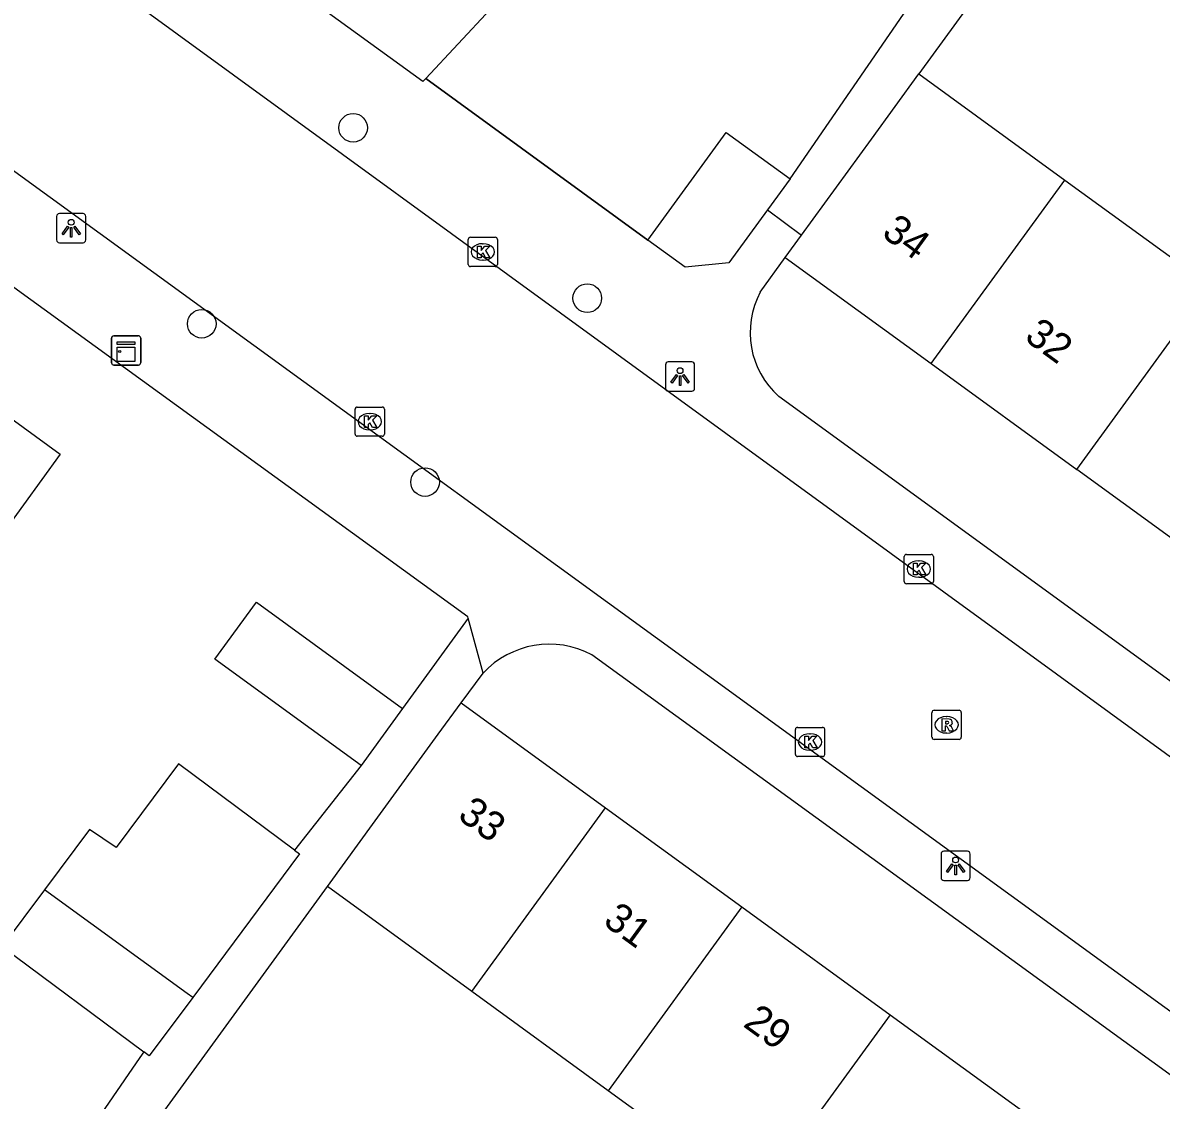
# Model space of a CAD drawing. Extents: x 159675 to 160530, y 382179 to 382901.
# Drawn here: x 160139.21 to 160178.13, y 382590.02 to 382626.86 of the extents above; entities that cross this region are included whole.
import ezdxf

# ---------------------------------------------------------------- set-up
doc = ezdxf.new("R2010")
doc.units = 0
for name, color, linetype in [('IMGEO_Boom', 7, 'Continuous'), ('IMGEO_Kast', 7, 'Continuous'), ('IMGEO_Kolk', 7, 'Continuous'), ('IMGEO_Lichtpunt', 7, 'Continuous'), ('IMGEO_Muur', 7, 'Continuous'), ('IMGEO_Pand', 7, 'Continuous'), ('IMGEO_Pand_nummerreeks', 7, 'Continuous'), ('IMGEO_Rijbaan_lokaal_open', 7, 'Continuous'), ('IMGEO_Rioolput', 7, 'Continuous'), ('IMGEO_Voetpad_open', 7, 'Continuous')]:
    doc.layers.add(name, color=color, linetype=linetype)

msp = doc.modelspace()

# ---------------------------------------------------------------- linework, layer by layer
at = {"layer": 'IMGEO_Boom'}
for centre in [(160150.503, 382623.268), (160158.508, 382617.444), (160145.327, 382616.568), (160152.962, 382611.156)]:
    msp.add_circle(centre, 0.489, dxfattribs=at)
at = {"layer": 'IMGEO_Kast'}
for p, q in [((160142.243, 382615.231), (160142.243, 382616.072)), ((160142.243, 382616.072), (160142.243, 382615.231)), ((160142.318, 382616.156), (160143.159, 382616.156)), ((160143.159, 382616.156), (160142.318, 382616.156)), ((160143.243, 382616.081), (160143.243, 382615.24)), ((160143.243, 382615.24), (160143.243, 382616.081)), ((160143.168, 382615.156), (160142.327, 382615.156)), ((160142.327, 382615.156), (160143.168, 382615.156))]:
    msp.add_line(p, q, dxfattribs=at)
for points in [[(160142.438, 382615.946), (160143.038, 382615.946), (160143.038, 382615.861), (160142.438, 382615.861), (160142.438, 382615.946)], [(160142.438, 382615.771), (160143.038, 382615.771), (160143.038, 382615.282), (160142.438, 382615.282), (160142.438, 382615.771)]]:
    msp.add_lwpolyline(points, dxfattribs=at)
msp.add_circle((160142.522, 382615.62), 0.0377, dxfattribs=at)
for centre, start, end in [((160142.321, 382616.078), 92.4484, 184.2845), ((160142.321, 382616.078), 92.4484, 184.2845), ((160143.165, 382616.078), 2.4484, 94.2845), ((160143.165, 382616.078), 2.4484, 94.2845), ((160142.321, 382615.234), 182.4484, 274.2845), ((160142.321, 382615.234), 182.4484, 274.2845), ((160143.165, 382615.234), 272.4484, 4.2845), ((160143.165, 382615.234), 272.4484, 4.2845)]:
    msp.add_arc(centre, 0.0779, start, end, dxfattribs=at)
at = {"layer": 'IMGEO_Kolk'}
for p, q in [((160154.51, 382619.526), (160155.362, 382619.526)), ((160154.435, 382618.6), (160154.435, 382619.452)), ((160154.923, 382619.306), (160154.948, 382619.306)), ((160155.436, 382619.452), (160155.436, 382618.6)), ((160154.946, 382618.746), (160154.921, 382618.746)), ((160155.362, 382618.526), (160154.51, 382618.526)), ((160150.646, 382613.723), (160151.498, 382613.723)), ((160150.571, 382612.797), (160150.571, 382613.649)), ((160151.059, 382613.503), (160151.084, 382613.503)), ((160151.572, 382613.649), (160151.572, 382612.797)), ((160151.082, 382612.943), (160151.057, 382612.943)), ((160151.498, 382612.723), (160150.646, 382612.723)), ((160169.415, 382608.682), (160170.267, 382608.682)), ((160169.34, 382607.756), (160169.34, 382608.608)), ((160169.828, 382608.462), (160169.853, 382608.462)), ((160170.341, 382608.608), (160170.341, 382607.756)), ((160169.851, 382607.902), (160169.826, 382607.902)), ((160170.267, 382607.682), (160169.415, 382607.682)), ((160165.621, 382601.846), (160165.621, 382602.698)), ((160165.696, 382602.772), (160166.548, 382602.772)), ((160166.109, 382602.552), (160166.134, 382602.552)), ((160166.622, 382602.698), (160166.622, 382601.846)), ((160166.548, 382601.772), (160165.696, 382601.772)), ((160166.132, 382601.992), (160166.107, 382601.992))]:
    msp.add_line(p, q, dxfattribs=at)
for points in [[(160154.51, 382619.526), (160155.362, 382619.526)], [(160154.435, 382618.6), (160154.435, 382619.452)], [(160154.756, 382619.226), (160154.879, 382619.226), (160154.879, 382619.075), (160155.009, 382619.226), (160155.173, 382619.226), (160155.027, 382619.075), (160155.18, 382618.826), (160155.028, 382618.826), (160154.943, 382618.99), (160154.879, 382618.923), (160154.879, 382618.826), (160154.756, 382618.826), (160154.756, 382619.226)], [(160155.436, 382619.452), (160155.436, 382618.6)], [(160155.362, 382618.526), (160154.51, 382618.526)], [(160150.646, 382613.723), (160151.498, 382613.723)], [(160150.571, 382612.797), (160150.571, 382613.649)], [(160150.892, 382613.423), (160151.015, 382613.423), (160151.015, 382613.272), (160151.145, 382613.423), (160151.309, 382613.423), (160151.163, 382613.272), (160151.316, 382613.023), (160151.164, 382613.023), (160151.079, 382613.187), (160151.015, 382613.12), (160151.015, 382613.023), (160150.892, 382613.023), (160150.892, 382613.423)], [(160151.572, 382613.649), (160151.572, 382612.797)], [(160151.498, 382612.723), (160150.646, 382612.723)], [(160169.415, 382608.682), (160170.267, 382608.682)], [(160169.34, 382607.756), (160169.34, 382608.608)], [(160169.661, 382608.382), (160169.784, 382608.382), (160169.784, 382608.231), (160169.914, 382608.382), (160170.078, 382608.382), (160169.932, 382608.231), (160170.085, 382607.982), (160169.933, 382607.982), (160169.848, 382608.146), (160169.784, 382608.079), (160169.784, 382607.982), (160169.661, 382607.982), (160169.661, 382608.382)], [(160170.341, 382608.608), (160170.341, 382607.756)], [(160170.267, 382607.682), (160169.415, 382607.682)], [(160165.621, 382601.846), (160165.621, 382602.698)], [(160165.696, 382602.772), (160166.548, 382602.772)], [(160165.942, 382602.472), (160166.065, 382602.472), (160166.065, 382602.321), (160166.195, 382602.472), (160166.359, 382602.472), (160166.213, 382602.321), (160166.366, 382602.072), (160166.214, 382602.072), (160166.129, 382602.236), (160166.065, 382602.169), (160166.065, 382602.072), (160165.942, 382602.072), (160165.942, 382602.472)], [(160166.622, 382602.698), (160166.622, 382601.846)], [(160166.548, 382601.772), (160165.696, 382601.772)]]:
    msp.add_lwpolyline(points, dxfattribs=at)
for centre, start, end in [((160154.512, 382619.45), 91.552, 178.448), ((160154.512, 382619.45), 91.552, 178.448), ((160155.36, 382619.45), 1.552, 88.448), ((160155.36, 382619.45), 1.552, 88.448), ((160154.512, 382618.602), 181.552, 268.448), ((160154.512, 382618.602), 181.552, 268.448), ((160155.36, 382618.602), 271.552, 358.448), ((160155.36, 382618.602), 271.552, 358.448), ((160150.648, 382613.647), 91.552, 178.448), ((160150.648, 382613.647), 91.552, 178.448), ((160151.496, 382613.647), 1.552, 88.448), ((160151.496, 382613.647), 1.552, 88.448), ((160150.648, 382612.799), 181.552, 268.448), ((160150.648, 382612.799), 181.552, 268.448), ((160151.496, 382612.799), 271.552, 358.448), ((160151.496, 382612.799), 271.552, 358.448), ((160169.417, 382608.606), 91.552, 178.448), ((160169.417, 382608.606), 91.552, 178.448), ((160170.265, 382608.606), 1.552, 88.448), ((160170.265, 382608.606), 1.552, 88.448), ((160169.417, 382607.758), 181.552, 268.448), ((160169.417, 382607.758), 181.552, 268.448), ((160170.265, 382607.758), 271.552, 358.448), ((160170.265, 382607.758), 271.552, 358.448), ((160165.698, 382602.696), 91.552, 178.448), ((160165.698, 382602.696), 91.552, 178.448), ((160166.546, 382602.696), 1.552, 88.448), ((160166.546, 382602.696), 1.552, 88.448), ((160165.698, 382601.848), 181.552, 268.448), ((160165.698, 382601.848), 181.552, 268.448), ((160166.546, 382601.848), 271.552, 358.448), ((160166.546, 382601.848), 271.552, 358.448)]:
    msp.add_arc(centre, 0.0765, start, end, dxfattribs=at)
for centre, major_axis, ratio, start_param, end_param in [((160154.922, 382619.026), (-0.387, 0.002), 0.722429, 4.712389, 7.853982), ((160154.947, 382619.026), (-0.39, 0.002), 0.717154, 1.570796, 4.712389), ((160151.058, 382613.223), (-0.387, 0.002), 0.722429, 4.712389, 7.853982), ((160151.083, 382613.223), (-0.39, 0.002), 0.717154, 1.570796, 4.712389), ((160169.827, 382608.182), (-0.387, 0.002), 0.722429, 4.712389, 7.853982), ((160169.852, 382608.182), (-0.39, 0.002), 0.717154, 1.570796, 4.712389), ((160166.108, 382602.272), (-0.387, 0.002), 0.722429, 4.712389, 7.853982), ((160166.133, 382602.272), (-0.39, 0.002), 0.717154, 1.570796, 4.712389)]:
    msp.add_ellipse(centre, major_axis=major_axis, ratio=ratio, start_param=start_param, end_param=end_param, dxfattribs=at)
at = {"layer": 'IMGEO_Lichtpunt'}
for p, q in [((160141.269, 382620.335), (160140.461, 382620.335)), ((160141.269, 382620.335), (160140.461, 382620.335)), ((160140.367, 382620.24), (160140.367, 382619.433)), ((160140.367, 382620.24), (160140.367, 382619.433)), ((160141.363, 382619.433), (160141.363, 382620.24)), ((160141.363, 382619.433), (160141.363, 382620.24)), ((160140.461, 382619.339), (160141.269, 382619.339)), ((160140.461, 382619.339), (160141.269, 382619.339)), ((160162.083, 382615.263), (160161.275, 382615.263)), ((160162.083, 382615.263), (160161.275, 382615.263)), ((160161.181, 382615.168), (160161.181, 382614.361)), ((160161.181, 382615.168), (160161.181, 382614.361)), ((160162.177, 382614.361), (160162.177, 382615.168)), ((160162.177, 382614.361), (160162.177, 382615.168)), ((160161.275, 382614.267), (160162.083, 382614.267)), ((160161.275, 382614.267), (160162.083, 382614.267)), ((160171.503, 382598.535), (160170.695, 382598.535)), ((160171.503, 382598.535), (160170.695, 382598.535)), ((160170.601, 382598.44), (160170.601, 382597.633)), ((160170.601, 382598.44), (160170.601, 382597.633)), ((160171.597, 382597.633), (160171.597, 382598.44)), ((160171.597, 382597.633), (160171.597, 382598.44)), ((160170.695, 382597.539), (160171.503, 382597.539)), ((160170.695, 382597.539), (160171.503, 382597.539))]:
    msp.add_line(p, q, dxfattribs=at)
for points in [[(160140.741, 382619.904), (160140.78, 382619.876), (160140.592, 382619.614), (160140.554, 382619.641), (160140.741, 382619.904)], [(160140.953, 382619.876), (160140.991, 382619.903), (160141.178, 382619.641), (160141.139, 382619.613), (160140.953, 382619.876)], [(160140.843, 382619.856), (160140.89, 382619.856), (160140.89, 382619.534), (160140.843, 382619.534), (160140.843, 382619.856)], [(160161.555, 382614.832), (160161.594, 382614.804), (160161.406, 382614.542), (160161.368, 382614.569), (160161.555, 382614.832)], [(160161.657, 382614.784), (160161.704, 382614.784), (160161.704, 382614.462), (160161.657, 382614.462), (160161.657, 382614.784)], [(160161.767, 382614.804), (160161.805, 382614.831), (160161.992, 382614.569), (160161.953, 382614.541), (160161.767, 382614.804)], [(160170.975, 382598.104), (160171.014, 382598.076), (160170.826, 382597.814), (160170.788, 382597.841), (160170.975, 382598.104)], [(160171.187, 382598.076), (160171.225, 382598.103), (160171.412, 382597.841), (160171.373, 382597.813), (160171.187, 382598.076)], [(160171.077, 382598.056), (160171.124, 382598.056), (160171.124, 382597.734), (160171.077, 382597.734), (160171.077, 382598.056)]]:
    msp.add_lwpolyline(points, dxfattribs=at)
for centre in [(160140.866, 382620.038), (160161.68, 382614.966), (160171.1, 382598.238)]:
    msp.add_circle(centre, 0.0994, dxfattribs=at)
for centre, start, end in [((160140.461, 382620.24), 90, 180), ((160140.461, 382620.24), 90, 180), ((160141.269, 382620.24), 0, 90), ((160141.269, 382620.24), 0, 90), ((160140.461, 382619.433), 180, 270), ((160140.461, 382619.433), 180, 270), ((160141.269, 382619.433), 270, 0), ((160141.269, 382619.433), 270, 360), ((160161.275, 382615.168), 90, 180), ((160161.275, 382615.168), 90, 180), ((160162.083, 382615.168), 0, 90), ((160162.083, 382615.168), 0, 90), ((160161.275, 382614.361), 180, 270), ((160161.275, 382614.361), 180, 270), ((160162.083, 382614.361), 270, 0), ((160162.083, 382614.361), 270, 360), ((160170.695, 382598.44), 90, 180), ((160170.695, 382598.44), 90, 180), ((160171.503, 382598.44), 0, 90), ((160171.503, 382598.44), 0, 90), ((160170.695, 382597.633), 180, 270), ((160170.695, 382597.633), 180, 270), ((160171.503, 382597.633), 270, 0), ((160171.503, 382597.633), 270, 360)]:
    msp.add_arc(centre, 0.0946, start, end, dxfattribs=at)
at = {"layer": 'IMGEO_Muur'}
msp.add_lwpolyline([(160160.579, 382619.432), (160152.983, 382624.952)], dxfattribs=at)
at = {"layer": 'IMGEO_Pand'}
for points in [[(160156.441, 382634.037), (160159.44, 382631.857), (160155.204, 382627.327), (160152.983, 382624.952)], [(160152.983, 382624.952), (160152.887, 382624.85), (160146.308, 382629.63)], [(160165.83, 382619.594), (160168.219, 382622.878), (160169.844, 382625.113)], [(160169.844, 382625.113), (160174.833, 382621.484)], [(160160.579, 382619.432), (160163.255, 382623.113), (160165.439, 382621.525)], [(160165.439, 382621.525), (160164.668, 382620.465)], [(160170.266, 382615.205), (160174.833, 382621.484)], [(160174.833, 382621.484), (160179.808, 382617.866)], [(160164.668, 382620.465), (160163.351, 382618.653), (160161.857, 382618.503), (160160.579, 382619.432)], [(160165.277, 382618.834), (160165.83, 382619.594)], [(160165.277, 382618.834), (160170.266, 382615.205)], [(160175.241, 382611.587), (160179.808, 382617.866)], [(160130.542, 382611.402), (160134.322, 382616.601), (160140.492, 382612.116), (160136.713, 382606.917)], [(160170.266, 382615.205), (160175.241, 382611.587)], [(160179.995, 382608.129), (160175.241, 382611.587)], [(160150.775, 382601.469), (160145.778, 382605.101), (160147.195, 382607.051), (160152.192, 382603.418)], [(160149.623, 382597.332), (160151.252, 382599.572), (160153.407, 382602.535), (160154.192, 382603.615)], [(160154.192, 382603.615), (160159.129, 382600.024)], [(160152.192, 382603.418), (160150.775, 382601.469)], [(160148.493, 382598.578), (160144.535, 382601.523), (160142.407, 382598.663), (160141.485, 382599.284), (160139.948, 382597.218)], [(160154.559, 382593.742), (160159.129, 382600.024)], [(160159.129, 382600.024), (160163.793, 382596.632)], [(160148.493, 382598.578), (160148.673, 382598.444), (160145.02, 382593.532)], [(160154.559, 382593.742), (160149.623, 382597.332)], [(160139.948, 382597.218), (160138.506, 382595.279), (160143.351, 382591.675)], [(160145.02, 382593.532), (160144.833, 382593.668), (160139.948, 382597.218)], [(160163.793, 382596.632), (160159.224, 382590.349)], [(160163.793, 382596.632), (160168.857, 382592.948)], [(160145.02, 382593.532), (160143.536, 382591.538), (160143.351, 382591.675)], [(160159.224, 382590.349), (160154.559, 382593.742)], [(160168.857, 382592.948), (160164.287, 382586.666)], [(160168.857, 382592.948), (160173.849, 382589.318)], [(160164.287, 382586.666), (160159.224, 382590.349)]]:
    msp.add_lwpolyline(points, dxfattribs=at)
at = {"layer": 'IMGEO_Rijbaan_lokaal_open'}
for points in [[(160245.716, 382552.786), (160140.763, 382629.192), (160140.555, 382629.351)], [(160136.439, 382623.587), (160136.712, 382623.379), (160240.412, 382548.029)]]:
    msp.add_lwpolyline(points, dxfattribs=at)
at = {"layer": 'IMGEO_Rioolput'}
for p, q in [((160170.291, 382602.432), (160170.291, 382603.284)), ((160170.366, 382603.358), (160171.218, 382603.358)), ((160171.292, 382603.284), (160171.292, 382602.432)), ((160170.779, 382603.138), (160170.804, 382603.138)), ((160170.802, 382602.578), (160170.777, 382602.578)), ((160171.218, 382602.358), (160170.366, 382602.358))]:
    msp.add_line(p, q, dxfattribs=at)
for points in [[(160170.291, 382602.432), (160170.291, 382603.284)], [(160170.366, 382603.358), (160171.218, 382603.358)], [(160171.292, 382603.284), (160171.292, 382602.432)], [(160170.88, 382603.056), (160170.628, 382603.058), (160170.628, 382602.658)], [(160170.628, 382602.658), (160170.752, 382602.658), (160170.752, 382602.82), (160170.763, 382602.82)], [(160170.806, 382602.977), (160170.752, 382602.977), (160170.752, 382602.896)], [(160170.752, 382602.896), (160170.804, 382602.896)], [(160170.81, 382602.791), (160170.881, 382602.658), (160171.021, 382602.658), (160170.956, 382602.784)], [(160171.218, 382602.358), (160170.366, 382602.358)]]:
    msp.add_lwpolyline(points, dxfattribs=at)
for centre, radius, start, end in [((160170.368, 382603.282), 0.0765, 91.552, 178.448), ((160170.368, 382603.282), 0.0765, 91.552, 178.448), ((160171.216, 382603.282), 0.0765, 1.552, 88.448), ((160171.216, 382603.282), 0.0765, 1.552, 88.448), ((160170.762, 382602.767), 0.0533, 26.0293, 88.6989), ((160170.788, 382603.085), 0.19, 274.7715, 282.9687), ((160170.812, 382602.881), 0.0964, 77.0061, 93.1865), ((160170.826, 382602.938), 0.0378, 276.6634, 79.6772), ((160170.879, 382602.946), 0.109, 350.3612, 89.416), ((160170.877, 382602.946), 0.112, 277.5842, 350.9817), ((160170.861, 382602.731), 0.108, 29.5134, 73.7905), ((160170.368, 382602.434), 0.0765, 181.552, 268.448), ((160170.368, 382602.434), 0.0765, 181.552, 268.448), ((160171.216, 382602.434), 0.0765, 271.552, 358.448), ((160171.216, 382602.434), 0.0765, 271.552, 358.448)]:
    msp.add_arc(centre, radius, start, end, dxfattribs=at)
for centre, major_axis, ratio, start_param, end_param in [((160170.778, 382602.858), (-0.387, 0.002), 0.722429, 4.712389, 7.853982), ((160170.803, 382602.858), (-0.39, 0.002), 0.717154, 1.570796, 4.712389)]:
    msp.add_ellipse(centre, major_axis=major_axis, ratio=ratio, start_param=start_param, end_param=end_param, dxfattribs=at)
at = {"layer": 'IMGEO_Voetpad_open'}
for points in [[(160180.693, 382633.904), (160177.781, 382636.024), (160169.844, 382625.113)], [(160165.439, 382621.525), (160170.173, 382628.407)], [(160152.983, 382624.952), (160160.579, 382619.432)], [(160154.437, 382606.506), (160154.426, 382606.548), (160133.33, 382621.844)], [(160164.668, 382620.465), (160165.83, 382619.594)], [(160164.421, 382617.647), (160165.277, 382618.834)], [(160222.117, 382573.829), (160221.524, 382573.013), (160165.053, 382614.084)], [(160154.437, 382606.506), (160152.192, 382603.418)], [(160154.946, 382604.626), (160154.437, 382606.506)], [(160214.457, 382563.306), (160215.141, 382564.235), (160158.66, 382605.256)], [(160154.192, 382603.615), (160154.946, 382604.626)], [(160150.775, 382601.469), (160148.493, 382598.578)], [(160144.775, 382584.11), (160141.693, 382586.428), (160149.623, 382597.332)], [(160143.351, 382591.675), (160143.206, 382591.48), (160139.394, 382585.922)]]:
    msp.add_lwpolyline(points, dxfattribs=at)
for centre, radius, start, end in [((160167, 382616.267), 2.925, 151.8521, 228.2648), ((160157.215, 382602.515), 3.099, 62.2002, 137.0545)]:
    msp.add_arc(centre, radius, start, end, dxfattribs=at)

# ---------------------------------------------------------------- texts
at = {"layer": 'IMGEO_Pand_nummerreeks'}
for s, rotation, p in [('34', 323.9695, (160168.532, 382619.582)), ('32', 323.9695, (160173.411, 382616.033)), ('33', 323.9701, (160154.035, 382599.673)), ('31', 323.9701, (160159.007, 382596.056)), ('29', 323.9701, (160163.797, 382592.572))]:
    msp.add_text(s, height=1, rotation=rotation, dxfattribs=at).set_placement(p)

doc.saveas('drawing.dxf')
